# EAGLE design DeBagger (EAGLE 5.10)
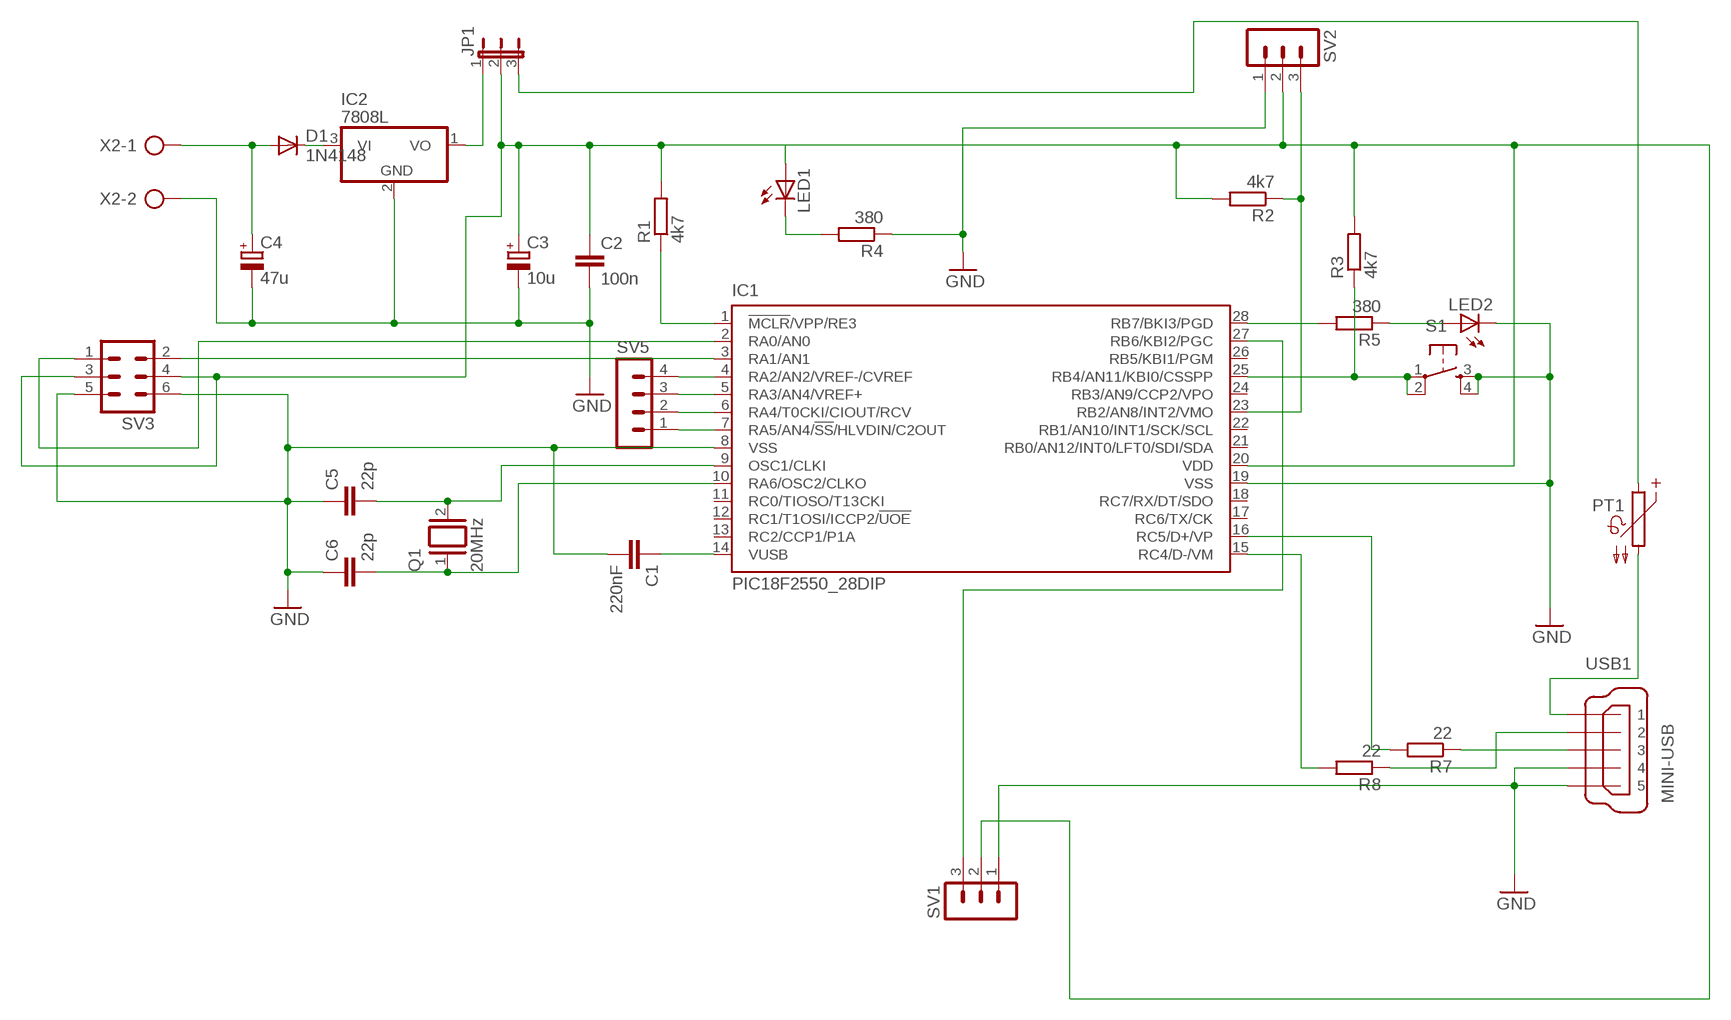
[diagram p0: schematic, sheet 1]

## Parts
C1  220nF  C-EU025-025X050  [C025-025X050]
C2  100n  C-EU025-025X050  [C025-025X050]
C3  10u  CPOL-EUE2,5-6E  [E2,5-6E]
C4  47u  CPOL-EUE2,5-6E  [E2,5-6E]
C5  22p  C-EU025-025X050  [C025-025X050]
C6  22p  C-EU025-025X050  [C025-025X050]
D1  1N4148  BAS15  [DO34-7]
IC1  PIC18F2550_28DIP  [DIL28-3]
IC2  7808L  [TO92]
JP1  JP2E  [JP2]
LED1  LED3MM  [LED3MM]
LED2  LED3MM  [LED3MM]
PT1  PTC660  [P660]
Q1  20MHz  XTAL/S  [QS]
R1  4k7  R-EU_0207/7  [0207/7]
R2  4k7  R-EU_0207/7  [0207/7]
R3  4k7  R-EU_0207/7  [0207/7]
R4  380  R-EU_0207/7  [0207/7]
R5  380  R-EU_0207/7  [0207/7]
R7  22  R-EU_0204/7  [0204/7]
R8  22  R-EU_0204/7  [0204/7]
S1  PRINTTASTER1  [PRINTTASTER1]
SV1  MA03-1  [MA03-1]
SV2  MA03-1  [MA03-1]
SV3  MA03-2  [MA03-2]
SV5  MA04-1  [MA04-1]
USB1  MINI-USB  MINI-USB_SHIELD5P2-32005-601  [32005-601]
X2  AK500/2  [AK500/2]

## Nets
GND: C1.2 C2.2 C3.- C4.- C5.1 C6.1 IC1.8(VSS) IC1.19(VSS) IC2.2(GND) LED2.K(C) R4.1 S1.3(S) S1.4(S1) SV1.1 SV2.1 SV3.5 SV3.6 USB1.4 USB1.5 X2.2
N$1: IC1.23(RB2/AN8/INT2/VMO) R2.1 SV2.3
N$2: IC1.2(RA0/AN0) SV3.1
N$3: C4.+ D1.A X2.1
N$4: LED1.K(C) R4.2
N$5: C6.2 IC1.10(RA6/OSC2/CLKO) Q1.1
N$6: IC1.28(RB7/BKI3/PGD) R5.2
N$7: LED2.A R5.1
N$8: D1.C IC2.3(VI)
N$9: C5.2 IC1.9(OSC1/CLKI) Q1.2
N$10: IC1.7(RA5/AN4/!SS!/HLVDIN/C2OUT) SV5.1
N$11: IC1.1(!MCLR!/VPP/RE3) R1.1
N$12: IC1.16(RC5/D+/VP) R7.2
N$13: IC1.15(RC4/D-/VM) R8.2
N$14: R7.1 USB1.3
N$15: R8.1 USB1.2
N$16: IC1.25(RB4/AN11/KBI0/CSSPP) R3.1 S1.1(P) S1.2(P1)
N$17: IC1.6(RA4/T0CKI/CIOUT/RCV) SV5.2
N$18: IC1.5(RA3/AN4/VREF+) SV5.3
N$19: C1.1 IC1.14(VUSB)
N$20: IC1.4(RA2/AN2/VREF-/CVREF) SV5.4
N$21: IC1.27(RB6/KBI2/PGC) SV1.3
N$22: IC1.3(RA1/AN1) SV3.2
N$24: IC2.1(VO) JP1.1
N$25: JP1.3 PT1.1
N$26: PT1.2 USB1.1
VDD: C2.1 C3.+ IC1.20(VDD) JP1.2 LED1.A R1.2 R2.2 R3.2 SV1.2 SV2.2 SV3.3 SV3.4
Unconnected: IC1.11(RC0/TIOSO/T13CKI) IC1.12(RC1/T1OSI/ICCP2/!UOE) IC1.13(RC2/CCP1/P1A) IC1.17(RC6/TX/CK) IC1.18(RC7/RX/DT/SDO) IC1.21(RB0/AN12/INT0/LFT0/SDI/SDA) IC1.22(RB1/AN10/INT1/SCK/SCL) IC1.24(RB3/AN9/CCP2/VPO) IC1.26(RB5/KBI1/PGM) USB1.M1(S1) USB1.M2(S2)

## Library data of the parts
C1 C2 C5 C6 = rcl:C-EU: CAPACITOR, European symbol
C3 C4 = rcl:CPOL-EU: POLARIZED CAPACITOR, European symbol
D1 = diode:BAS15: DIODE
IC1 = microchip:PIC18F2*_28: USB Microcontrollers with nanoWatt Technology High-Performance, Enhanced Flash, 28/40/44-Pin, Source: http://ww1.microchip.com/downloads/en/devicedoc/39632c.pdf
IC2 = linear:78*: Positive VOLTAGE REGULATOR Source: http://cache.national.com/ds/LM/LM78L05.pdf http://www.fairchildsemi.com/ds/LM/LM7805.pdf
JP1 = jumper:JP2E: JUMPER
LED1 LED2 = led:LED: LED
PT1 = ptc-ntc:PTC660: PHILIPS PTC
Q1 = special:XTAL/S: CRYSTAL
R1-R5 R7 R8 = rcl:R-EU_: RESISTOR, European symbol
S1 = Taster:PRINTTASTER1
SV1 SV2 = con-lstb:MA03-1: PIN HEADER
SV3 = con-lstb:MA03-2: PIN HEADER
SV5 = con-lstb:MA04-1: PIN HEADER
USB1 = con-cypressindustries:MINI-USB_SHIELD5P2-: MINI USB-B R/A DIP 5pol. Source: www.cypressindustries.com
X2 = con-ptr500:AK500/2: CONNECTOR

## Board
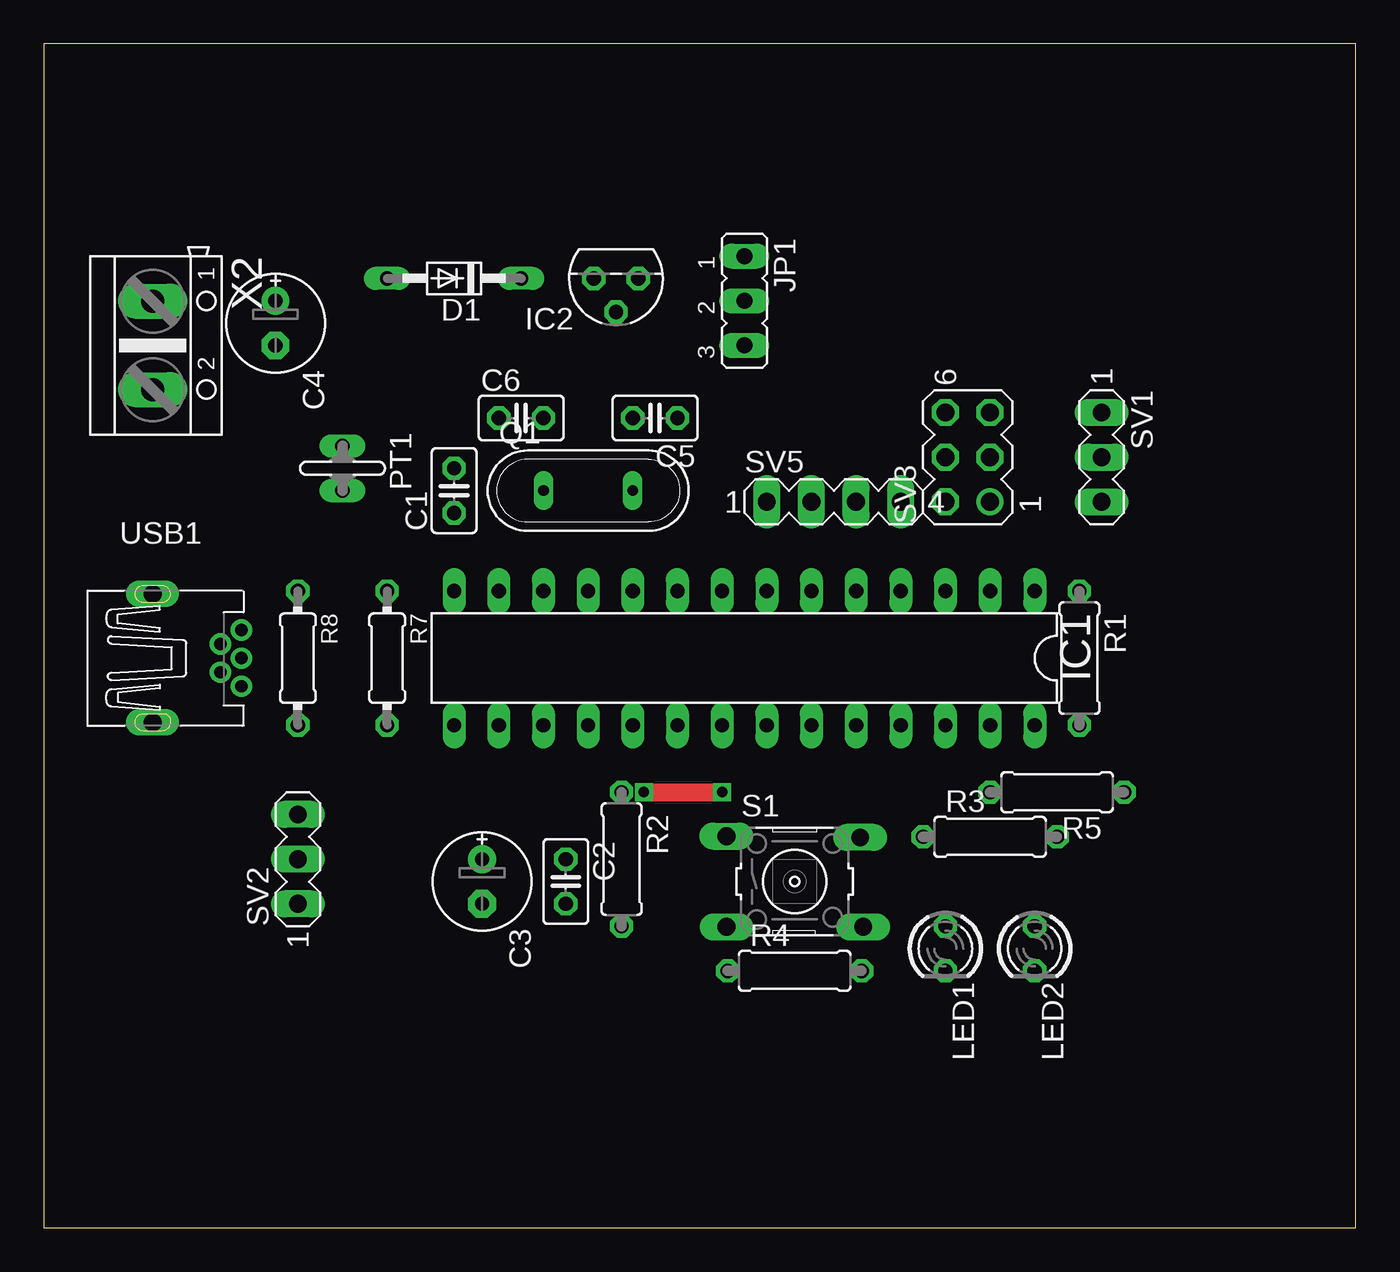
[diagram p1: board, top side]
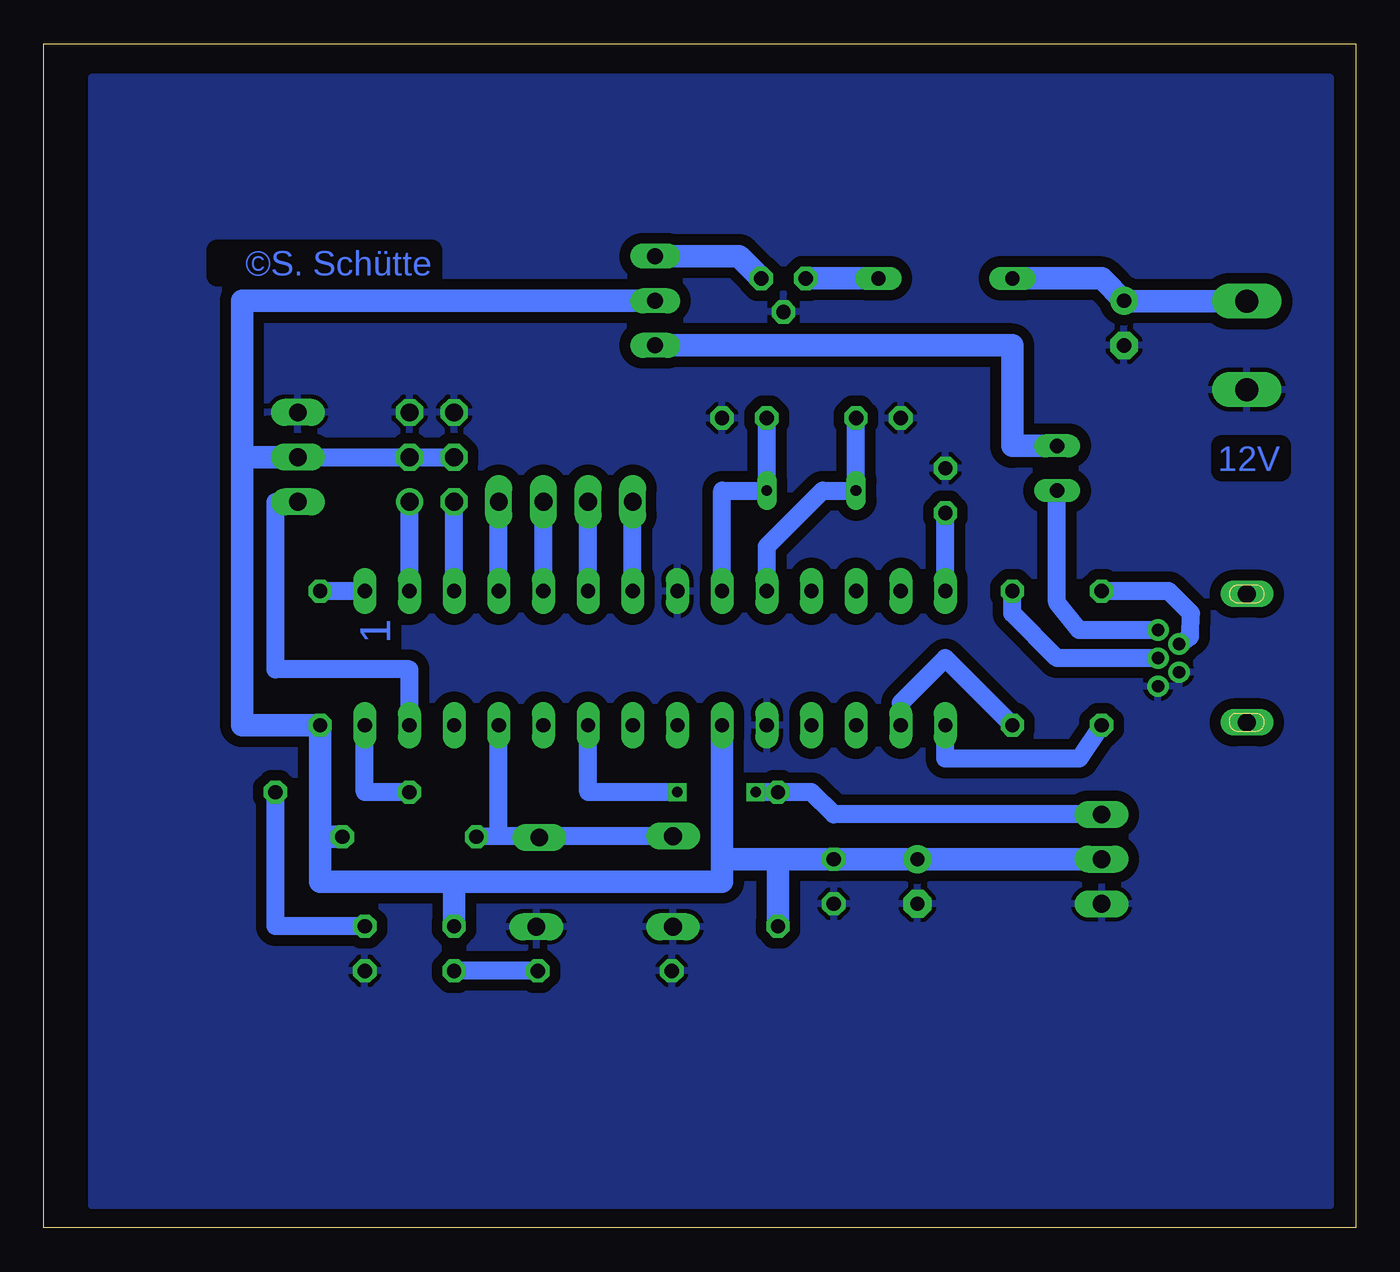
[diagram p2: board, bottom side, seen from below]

Size 74.6 x 67.3 mm. Coordinates in mm from the lower left corner, seen from the top.
Outline: 0,0 74.6,0 74.6,67.3 0,67.3 0,0
Copper layers (1*16): Top 0.035mm / dielectric 1.5mm / Bottom 0.035mm
Design rules "default": minimum track width 10mil, minimum drill 24mil, track to track 8mil, track to pad 8mil, pad to pad 8mil, via to via 8mil, smd to smd 8mil, copper to edge 40mil, drill to drill 8mil, minimum pad ring 10mil, minimum via ring 8mil, stop-mask expansion 4mil, vias tented up to drill 0mil, thermal gap 10mil

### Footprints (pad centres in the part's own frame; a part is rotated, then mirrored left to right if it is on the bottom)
C025-025X050 = drill 0.813 octagon: 1 -1.27,0; 2 1.27,0
E2,5-6E = drill 0.813 pad 1.575 round: + -1.27,0 | drill 0.813 pad 1.575 octagon: - 1.27,0
DO34-7 = drill 0.813 long: A 3.81,0; C -3.81,0
DIL28-3 = drill 0.813 long: 1 -16.51,-3.81; 2 -13.97,-3.81; 3 -11.43,-3.81; 4 -8.89,-3.81; 5 -6.35,-3.81; 6 -3.81,-3.81; 7 -1.27,-3.81; 8 1.27,-3.81; 9 3.81,-3.81; 10 6.35,-3.81; 11 8.89,-3.81; 12 11.43,-3.81; 13 13.97,-3.81; 14 16.51,-3.81; 15 16.51,3.81; 16 13.97,3.81; 17 11.43,3.81; 18 8.89,3.81; 19 6.35,3.81; 20 3.81,3.81; 21 1.27,3.81; 22 -1.27,3.81; 23 -3.81,3.81; 24 -6.35,3.81; 25 -8.89,3.81; 26 -11.43,3.81; 27 -13.97,3.81; 28 -16.51,3.81
TO92 = drill 0.813 octagon: 1 -1.27,0; 2 0,1.905; 3 1.27,0
JP2 = drill 0.914 long: 1 -2.54,0; 2 0,0; 3 2.54,0
LED3MM = drill 0.813 octagon: A -1.27,0; K 1.27,0
P660 = drill 0.813 long: 1 -1.27,0; 2 1.27,0
QS = drill 0.61 long: 1 -2.54,0; 2 2.54,0
0207/7 = drill 0.813 octagon: 1 -3.81,0; 2 3.81,0
0204/7 = drill 0.813 octagon: 1 -3.81,0; 2 3.81,0
PRINTTASTER1 = drill 1.016 long: 1 -3.885,2.578; 2 3.731,2.502; 3 -3.881,-2.578; 4 3.897,-2.578
MA03-1 = drill 1.016 long: 1 -2.54,0; 2 0,0; 3 2.54,0
MA03-2 = drill 1.016 round: 1 -2.54,-1.27 | drill 1.016 octagon: 2 -2.54,1.27; 3 0,-1.27; 4 0,1.27; 5 2.54,-1.27; 6 2.54,1.27
MA04-1 = drill 1.016 long: 1 -3.81,0; 2 -1.27,0; 3 1.27,0; 4 3.81,0
32005-601 = drill 0.7 pad 1.016 round: 1 2.825,1.6; 2 1.625,0.8; 3 2.825,0; 4 1.625,-0.8; 5 2.825,-1.6 | drill 1 pad 1.422 long: M1 -2.225,3.65; M2 -2.225,-3.65
AK500/2 = drill 1.321 long: 1 -2.515,0; 2 2.515,0

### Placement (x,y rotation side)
C1  23.33,41.91 90 top
C2  29.68,19.68 270 top
C3  24.92,19.68 270 top
C4  13.17,51.43 270 top
C5  34.76,46.03 180 top
C6  27.14,46.03 0 top
D1  23.33,53.97 180 top
IC1  39.84,32.38 180 top
IC2  32.54,53.97 180 top
JP1  39.84,52.7 270 top
LED1  51.27,15.87 270 top
LED2  56.35,15.87 270 top
PT1  16.98,43.17 270 top
Q1  30.95,41.91 0 top
R1  58.89,32.38 270 top
R2  32.85,20.95 270 top
R3  53.81,22.22 0 top
R4  42.7,14.6 0 top
R5  57.62,24.76 180 top
R7  19.52,32.38 270 top
R8  14.44,32.38 270 top
S1  42.7,19.68 0 top
SV1  60.16,43.81 270 top
SV2  14.44,20.95 90 top
SV3  52.54,43.81 90 top
SV5  44.92,41.27 0 top
USB1  8.41,32.38 0 top
X2  6.19,50.16 270 top

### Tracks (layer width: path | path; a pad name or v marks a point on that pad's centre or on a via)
GND
  pour Bottom (isolate 0.61): 71.91,1.27 1.42,1.27 1.42,65.4 71.91,65.4
N$1  (via drill 0.6)
  Top 1.016: v34.12,24.76 v38.57,24.76
  Bottom 1.016: v38.57,24.76 43.65,24.76 IC1.23 | v34.12,24.76 R2.1 30.95,24.76 29.68,23.49 SV2.3
N$2
  Bottom 1.016: IC1.2 SV3.1
N$3
  Bottom 1.016: 13.17,52.67 C4.+
  Bottom 1.27: X2.1 13.17,52.67 | C4.+ 14.44,53.97 D1.A
N$4
  Bottom 1.016: R4.2 LED1.K
N$5
  Bottom 1.016: IC1.10 33.49,38.73 30.31,41.91 Q1.1 C6.2
N$6
  Bottom 1.016: R5.2 56.35,24.76 IC1.28
N$7
  Bottom 1.016: R5.1 61.43,17.14 LED2.A
N$8
  Bottom 1.27: D1.C IC2.3
N$9
  Bottom 1.016: IC1.9 36.03,41.91 Q1.2 C5.2
N$10
  Bottom 1.016: IC1.7 SV5.1
N$11
  Bottom 1.016: IC1.1 R1.1
N$12
  Bottom 1.016: IC1.16 25.87,29.84 23.33,32.38 R7.2
N$13
  Bottom 1.016: IC1.15 23.33,26.67 15.71,26.67 R8.2
N$14
  Bottom 1.016: USB1.3 16.98,32.38 19.52,34.92 R7.1
N$15
  Bottom 1.016: R8.1 10.63,36.19 9.36,34.92 9.4,33.61 USB1.2
N$16
  Bottom 0.813: S1.2 47.46,22.18 48.73,22.26
  Bottom 1.016: 48.73,22.26 IC1.25 | S1.1 48.73,22.26 | 48.73,22.26 R3.1
N$17
  Bottom 1.016: IC1.6 SV5.2
N$18
  Bottom 1.016: IC1.5 SV5.3
N$19
  Bottom 1.016: IC1.14 C1.1
N$20
  Bottom 1.016: IC1.4 SV5.4
N$21
  Bottom 1.016: SV1.3 61.43,41.27 61.43,31.75 53.81,31.75 IC1.27
N$22
  Bottom 1.016: IC1.3 SV3.2
N$24
  Bottom 1.27: IC2.1 35.08,55.24 JP1.1
N$25
  Bottom 1.27: PT1.1 19.52,44.45 19.52,50.16 JP1.3
N$26
  Bottom 1.016: USB1.1 15.71,33.98 16.98,35.55 PT1.2
VDD
  Bottom 1.016: SV1.2 SV3.3 SV3.4
  Bottom 1.27: 58.89,22.22 R1.2 63.34,28.57 63.34,43.81 | 36.03,20.95 IC1.20 | 32.85,20.95 36.03,20.95 | 32.85,20.95 R2.2 | SV2.2 C3.+ C2.1 32.85,20.95 | 58.89,22.22 58.89,19.68 51.27,19.68 | 58.89,22.22 R3.2 | 36.03,20.95 36.03,19.68 51.27,19.68 | 51.27,19.68 LED1.A | 63.34,43.81 SV1.2 | JP1.2 63.34,52.7 63.34,43.81

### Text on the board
Bottom: ©S. Schütte | 12V | 1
